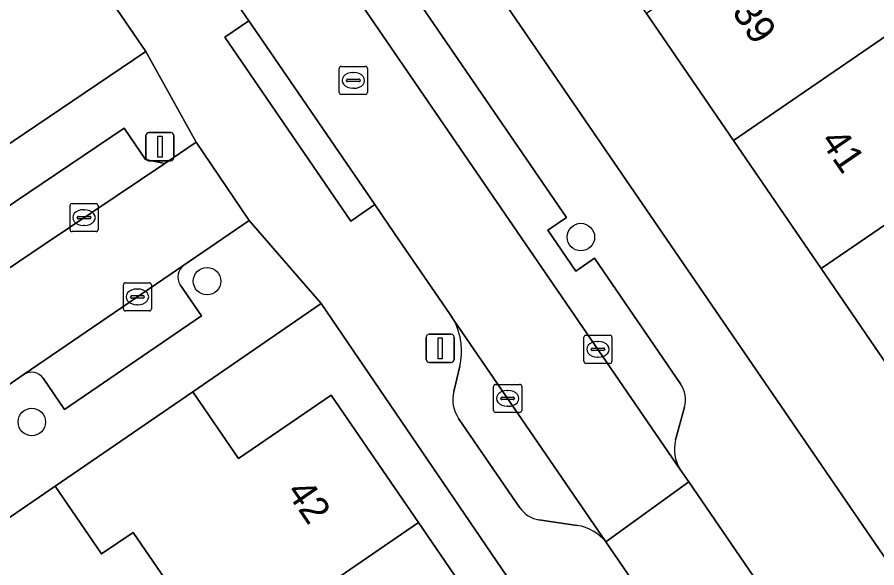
# Model space of a CAD drawing. Extents: x 157445 to 158888, y 383061 to 384688.
# Drawn here: x 158174.58 to 158205.18, y 383757.8 to 383777.4 of the extents above; entities that cross this region are included whole.
import ezdxf

# ---------------------------------------------------------------- set-up
doc = ezdxf.new("R2010")
doc.units = 0
for name, color, linetype in [('IMGEO_Boom', 7, 'Continuous'), ('IMGEO_Erf', 7, 'Continuous'), ('IMGEO_Kolk', 7, 'Continuous'), ('IMGEO_Lichtmast', 7, 'Continuous'), ('IMGEO_Pand', 7, 'Continuous'), ('IMGEO_Pand_nummerreeks', 7, 'Continuous'), ('IMGEO_Parkeervlak_open', 7, 'Continuous'), ('IMGEO_Rijbaan_lokaal_open', 7, 'Continuous'), ('IMGEO_Rioolput', 7, 'Continuous'), ('IMGEO_Voetpad_open', 7, 'Continuous')]:
    doc.layers.add(name, color=color, linetype=linetype)

msp = doc.modelspace()

# ---------------------------------------------------------------- linework, layer by layer
at = {"layer": 'IMGEO_Boom'}
for centre in [(158194.645, 383769.577), (158181.34, 383768.007), (158175.105, 383762.994)]:
    msp.add_circle(centre, 0.489, dxfattribs=at)
at = {"layer": 'IMGEO_Erf'}
for points in [[(158170.104, 383780.453), (158173.189, 383775.937), (158170.075, 383773.81), (158171.837, 383771.231), (158179.168, 383776.179), (158157.348, 383808.015)], [(158181.791, 383754.566), (158178.707, 383759.066), (158177.586, 383758.297), (158175.939, 383760.709), (158169.708, 383756.443)]]:
    msp.add_lwpolyline(points, dxfattribs=at)
for points in [[(158203.195, 383768.457), (158200.072, 383773.02), (158196.983, 383777.534), (158193.766, 383782.235), (158190.646, 383786.793), (158187.607, 383791.234), (158186.163, 383793.349), (158182.895, 383791.111), (158211.057, 383750), (158215.044, 383744.012), (158218.397, 383746.244), (158215.826, 383750), (158215.286, 383750.789), (158212.326, 383755.115), (158209.334, 383759.486), (158206.199, 383764.067)], [(158185.753, 383763.949), (158188.863, 383759.413), (158191.92, 383754.953), (158195.167, 383750.218), (158195.316, 383750), (158198.201, 383745.792), (158201.232, 383741.371), (158204.427, 383736.711), (158205.617, 383737.521), (158197.119, 383750), (158185.398, 383767.212), (158180.833, 383764.065), (158182.46, 383761.691)]]:
    msp.add_lwpolyline(points, close=True, dxfattribs=at)
at = {"layer": 'IMGEO_Kolk'}
for p, q in [((158176.464, 383769.844), (158176.464, 383770.696)), ((158176.539, 383770.77), (158177.391, 383770.77)), ((158177.465, 383770.696), (158177.465, 383769.844)), ((158176.952, 383770.55), (158176.977, 383770.55)), ((158176.723, 383770.264), (158176.723, 383770.276)), ((158177.161, 383770.227), (158176.763, 383770.227)), ((158176.766, 383770.313), (158177.164, 383770.313)), ((158177.207, 383770.276), (158177.207, 383770.264)), ((158176.975, 383769.99), (158176.95, 383769.99)), ((158177.391, 383769.77), (158176.539, 383769.77)), ((158178.437, 383767.948), (158179.289, 383767.948)), ((158178.362, 383767.022), (158178.362, 383767.874)), ((158178.85, 383767.728), (158178.875, 383767.728)), ((158179.363, 383767.874), (158179.363, 383767.022)), ((158178.621, 383767.442), (158178.621, 383767.454)), ((158179.059, 383767.405), (158178.661, 383767.405)), ((158178.664, 383767.491), (158179.062, 383767.491)), ((158179.105, 383767.454), (158179.105, 383767.442)), ((158178.873, 383767.168), (158178.848, 383767.168)), ((158179.289, 383766.948), (158178.437, 383766.948)), ((158194.751, 383765.156), (158194.751, 383766.008)), ((158194.826, 383766.082), (158195.678, 383766.082)), ((158195.239, 383765.862), (158195.264, 383765.862)), ((158195.752, 383766.008), (158195.752, 383765.156)), ((158195.01, 383765.576), (158195.01, 383765.588)), ((158195.448, 383765.539), (158195.05, 383765.539)), ((158195.053, 383765.625), (158195.451, 383765.625)), ((158195.494, 383765.588), (158195.494, 383765.576)), ((158195.262, 383765.302), (158195.237, 383765.302)), ((158195.678, 383765.082), (158194.826, 383765.082)), ((158191.612, 383764.333), (158192.464, 383764.333)), ((158191.537, 383763.407), (158191.537, 383764.259)), ((158192.025, 383764.113), (158192.05, 383764.113)), ((158192.538, 383764.259), (158192.538, 383763.407)), ((158191.796, 383763.827), (158191.796, 383763.839)), ((158192.234, 383763.79), (158191.836, 383763.79)), ((158191.839, 383763.876), (158192.237, 383763.876)), ((158192.28, 383763.839), (158192.28, 383763.827)), ((158192.048, 383763.553), (158192.023, 383763.553)), ((158192.464, 383763.333), (158191.612, 383763.333))]:
    msp.add_line(p, q, dxfattribs=at)
for points in [[(158176.464, 383769.844), (158176.464, 383770.696)], [(158176.539, 383770.77), (158177.391, 383770.77)], [(158177.465, 383770.696), (158177.465, 383769.844)], [(158177.391, 383769.77), (158176.539, 383769.77)], [(158178.437, 383767.948), (158179.289, 383767.948)], [(158178.362, 383767.022), (158178.362, 383767.874)], [(158179.363, 383767.874), (158179.363, 383767.022)], [(158179.289, 383766.948), (158178.437, 383766.948)], [(158194.751, 383765.156), (158194.751, 383766.008)], [(158194.826, 383766.082), (158195.678, 383766.082)], [(158195.752, 383766.008), (158195.752, 383765.156)], [(158195.678, 383765.082), (158194.826, 383765.082)], [(158191.612, 383764.333), (158192.464, 383764.333)], [(158191.537, 383763.407), (158191.537, 383764.259)], [(158192.538, 383764.259), (158192.538, 383763.407)], [(158192.464, 383763.333), (158191.612, 383763.333)]]:
    msp.add_lwpolyline(points, dxfattribs=at)
for centre, radius, start, end in [((158176.541, 383770.694), 0.0765, 91.552, 178.448), ((158176.541, 383770.694), 0.0765, 91.552, 178.448), ((158177.389, 383770.694), 0.0765, 1.552, 88.448), ((158177.389, 383770.694), 0.0765, 1.552, 88.448), ((158176.763, 383770.273), 0.0403, 85.8775, 175.7526), ((158176.76, 383770.263), 0.0366, 178.938, 274.7102), ((158177.164, 383770.27), 0.043, 264.8664, 352.4533), ((158177.168, 383770.275), 0.0386, 1.7309, 96.639), ((158176.541, 383769.846), 0.0765, 181.552, 268.448), ((158176.541, 383769.846), 0.0765, 181.552, 268.448), ((158177.389, 383769.846), 0.0765, 271.552, 358.448), ((158177.389, 383769.846), 0.0765, 271.552, 358.448), ((158178.439, 383767.872), 0.0765, 91.552, 178.448), ((158178.439, 383767.872), 0.0765, 91.552, 178.448), ((158179.287, 383767.872), 0.0765, 1.552, 88.448), ((158179.287, 383767.872), 0.0765, 1.552, 88.448), ((158178.661, 383767.451), 0.0403, 85.8775, 175.7526), ((158178.658, 383767.441), 0.0366, 178.938, 274.7102), ((158179.062, 383767.448), 0.043, 264.8664, 352.4533), ((158179.066, 383767.453), 0.0386, 1.7309, 96.639), ((158178.439, 383767.024), 0.0765, 181.552, 268.448), ((158178.439, 383767.024), 0.0765, 181.552, 268.448), ((158179.287, 383767.024), 0.0765, 271.552, 358.448), ((158179.287, 383767.024), 0.0765, 271.552, 358.448), ((158194.828, 383766.006), 0.0765, 91.552, 178.448), ((158194.828, 383766.006), 0.0765, 91.552, 178.448), ((158195.676, 383766.006), 0.0765, 1.552, 88.448), ((158195.676, 383766.006), 0.0765, 1.552, 88.448), ((158195.05, 383765.585), 0.0403, 85.8775, 175.7526), ((158195.047, 383765.575), 0.0366, 178.938, 274.7102), ((158195.451, 383765.582), 0.043, 264.8664, 352.4533), ((158195.455, 383765.587), 0.0386, 1.7309, 96.639), ((158194.828, 383765.158), 0.0765, 181.552, 268.448), ((158194.828, 383765.158), 0.0765, 181.552, 268.448), ((158195.676, 383765.158), 0.0765, 271.552, 358.448), ((158195.676, 383765.158), 0.0765, 271.552, 358.448), ((158191.614, 383764.257), 0.0765, 91.552, 178.448), ((158191.614, 383764.257), 0.0765, 91.552, 178.448), ((158192.462, 383764.257), 0.0765, 1.552, 88.448), ((158192.462, 383764.257), 0.0765, 1.552, 88.448), ((158191.836, 383763.836), 0.0403, 85.8775, 175.7526), ((158191.833, 383763.826), 0.0366, 178.938, 274.7102), ((158192.237, 383763.833), 0.043, 264.8664, 352.4533), ((158192.241, 383763.838), 0.0386, 1.7309, 96.639), ((158191.614, 383763.409), 0.0765, 181.552, 268.448), ((158191.614, 383763.409), 0.0765, 181.552, 268.448), ((158192.462, 383763.409), 0.0765, 271.552, 358.448), ((158192.462, 383763.409), 0.0765, 271.552, 358.448)]:
    msp.add_arc(centre, radius, start, end, dxfattribs=at)
for centre, major_axis, ratio, start_param, end_param in [((158176.951, 383770.27), (-0.387, 0.002), 0.722429, 4.712389, 7.853982), ((158176.976, 383770.27), (-0.39, 0.002), 0.717154, 1.570796, 4.712389), ((158178.849, 383767.448), (-0.387, 0.002), 0.722429, 4.712389, 7.853982), ((158178.874, 383767.448), (-0.39, 0.002), 0.717154, 1.570796, 4.712389), ((158195.238, 383765.582), (-0.387, 0.002), 0.722429, 4.712389, 7.853982), ((158195.263, 383765.582), (-0.39, 0.002), 0.717154, 1.570796, 4.712389), ((158192.024, 383763.833), (-0.387, 0.002), 0.722429, 4.712389, 7.853982), ((158192.049, 383763.833), (-0.39, 0.002), 0.717154, 1.570796, 4.712389)]:
    msp.add_ellipse(centre, major_axis=major_axis, ratio=ratio, start_param=start_param, end_param=end_param, dxfattribs=at)
at = {"layer": 'IMGEO_Lichtmast'}
for p, q in [((158179.168, 383772.395), (158179.168, 383773.195)), ((158179.168, 383773.195), (158179.168, 383772.395)), ((158179.268, 383773.295), (158180.058, 383773.295)), ((158180.058, 383773.295), (158179.268, 383773.295)), ((158180.158, 383773.195), (158180.158, 383772.395)), ((158180.158, 383772.395), (158180.158, 383773.195)), ((158180.058, 383772.295), (158179.268, 383772.295)), ((158179.268, 383772.295), (158180.058, 383772.295)), ((158189.243, 383766.117), (158190.033, 383766.117)), ((158190.033, 383766.117), (158189.243, 383766.117)), ((158189.143, 383765.217), (158189.143, 383766.017)), ((158189.143, 383766.017), (158189.143, 383765.217)), ((158190.133, 383766.017), (158190.133, 383765.217)), ((158190.133, 383765.217), (158190.133, 383766.017)), ((158190.033, 383765.117), (158189.243, 383765.117)), ((158189.243, 383765.117), (158190.033, 383765.117))]:
    msp.add_line(p, q, dxfattribs=at)
for points in [[(158179.588, 383773.17), (158179.738, 383773.17), (158179.738, 383772.42), (158179.588, 383772.42), (158179.588, 383773.17)], [(158189.563, 383765.992), (158189.713, 383765.992), (158189.713, 383765.242), (158189.563, 383765.242), (158189.563, 383765.992)]]:
    msp.add_lwpolyline(points, dxfattribs=at)
for centre, start, end in [((158179.268, 383773.195), 90, 180), ((158179.268, 383773.195), 90, 180), ((158180.058, 383773.195), 0, 90), ((158180.058, 383773.195), 360, 90), ((158179.268, 383772.395), 180, 270), ((158179.268, 383772.395), 180, 270), ((158180.058, 383772.395), 270, 0), ((158180.058, 383772.395), 270, 0), ((158189.243, 383766.017), 90, 180), ((158189.243, 383766.017), 90, 180), ((158190.033, 383766.017), 0, 90), ((158190.033, 383766.017), 360, 90), ((158189.243, 383765.217), 180, 270), ((158189.243, 383765.217), 180, 270), ((158190.033, 383765.217), 270, 0), ((158190.033, 383765.217), 270, 0)]:
    msp.add_arc(centre, 0.1, start, end, dxfattribs=at)
at = {"layer": 'IMGEO_Pand'}
for points in [[(158196.983, 383777.534), (158200.072, 383773.02), (158207.24, 383777.926), (158205.809, 383780.015), (158209.195, 383782.334), (158207.537, 383784.757), (158204.149, 383782.438)], [(158207.24, 383777.926), (158200.072, 383773.02), (158203.195, 383768.457), (158210.365, 383773.364)], [(158206.199, 383764.067), (158213.371, 383768.976), (158210.365, 383773.364), (158203.195, 383768.457)], [(158188.863, 383759.413), (158185.753, 383763.949), (158182.46, 383761.691), (158180.833, 383764.065), (158175.939, 383760.709), (158177.586, 383758.297), (158178.707, 383759.066), (158181.791, 383754.566)], [(158184.848, 383750.106), (158191.92, 383754.953), (158188.863, 383759.413), (158181.791, 383754.566)]]:
    msp.add_lwpolyline(points, close=True, dxfattribs=at)
at = {"layer": 'IMGEO_Parkeervlak_open'}
for points in [[(158180.633, 383786.925), (158198.181, 383761.303)], [(158198.194, 383764.347), (158195.13, 383768.82), (158194.463, 383768.363), (158193.465, 383769.82), (158194.133, 383770.277), (158186.834, 383780.933), (158186.166, 383780.475), (158185.336, 383781.687), (158186.005, 383782.145), (158183.563, 383785.71)], [(158174.159, 383768.371), (158175.539, 383769.31), (158179.837, 383772.198), (158179.151, 383772.335), (158178.389, 383773.452), (158173.531, 383770.179), (158174.291, 383769.066)], [(158180.511, 383768.576), (158174.828, 383764.691)], [(158175.508, 383764.55), (158176.268, 383763.437), (158181.14, 383766.768), (158180.38, 383767.881)], [(158195.535, 383758.724), (158190.126, 383766.615)], [(158190.334, 383764.979), (158190.119, 383764.083)], [(158198.017, 383762.354), (158198.334, 383763.519)], [(158190.295, 383763.124), (158192.476, 383759.938)], [(158193.154, 383759.513), (158194.513, 383759.311)]]:
    msp.add_lwpolyline(points, dxfattribs=at)
for centre, radius, start, end in [((158180.831, 383768.156), 0.528, 127.2771, 211.3741), ((158188.074, 383765.523), 2.324, 346.4646, 28.0267), ((158175.094, 383764.265), 0.502, 34.555, 122.0161), ((158197.367, 383763.781), 1.002, 344.82, 34.3739), ((158191.284, 383763.801), 1.198, 166.3903, 214.4086), ((158199.276, 383762.012), 1.304, 164.8054, 212.9327), ((158193.304, 383760.506), 1.005, 214.4507, 261.3867), ((158194.267, 383757.699), 1.631, 38.943, 81.314)]:
    msp.add_arc(centre, radius, start, end, dxfattribs=at)
at = {"layer": 'IMGEO_Rijbaan_lokaal_open'}
for points in [[(158179.656, 383781.899), (158179.858, 383781.604), (158182.01, 383778.474), (158182.833, 383777.276), (158183.462, 383776.361), (158187.315, 383770.733), (158188.017, 383769.707), (158189.996, 383766.816), (158190.126, 383766.615), (158195.535, 383758.724), (158198.486, 383760.859), (158198.181, 383761.303), (158180.633, 383786.925), (158176.948, 383792.302), (158167.359, 383806.297), (158164.805, 383810.025), (158161.728, 383807.983), (158162.085, 383807.463)], [(158174.159, 383768.371), (158172.941, 383767.542), (158164.897, 383762.069), (158163.604, 383761.185), (158165.587, 383758.374), (158167.014, 383759.349), (158173.626, 383763.869), (158174.828, 383764.691), (158180.511, 383768.576), (158182.841, 383770.169), (158180.957, 383772.951), (158179.837, 383772.198), (158175.539, 383769.31)], [(158200.771, 383757.522), (158198.486, 383760.859), (158195.535, 383758.724), (158197.821, 383755.384)]]:
    msp.add_lwpolyline(points, close=True, dxfattribs=at)
at = {"layer": 'IMGEO_Rioolput'}
for p, q in [((158186.121, 383775.653), (158186.973, 383775.653)), ((158186.046, 383774.727), (158186.046, 383775.579)), ((158186.534, 383775.433), (158186.559, 383775.433)), ((158187.047, 383775.579), (158187.047, 383774.727)), ((158186.305, 383775.147), (158186.305, 383775.159)), ((158186.743, 383775.11), (158186.345, 383775.11)), ((158186.348, 383775.196), (158186.746, 383775.196)), ((158186.789, 383775.159), (158186.789, 383775.147)), ((158186.557, 383774.873), (158186.532, 383774.873)), ((158186.973, 383774.653), (158186.121, 383774.653))]:
    msp.add_line(p, q, dxfattribs=at)
for points in [[(158186.121, 383775.653), (158186.973, 383775.653)], [(158186.046, 383774.727), (158186.046, 383775.579)], [(158187.047, 383775.579), (158187.047, 383774.727)], [(158186.973, 383774.653), (158186.121, 383774.653)]]:
    msp.add_lwpolyline(points, dxfattribs=at)
for centre, radius, start, end in [((158186.123, 383775.577), 0.0765, 91.552, 178.448), ((158186.123, 383775.577), 0.0765, 91.552, 178.448), ((158186.971, 383775.577), 0.0765, 1.552, 88.448), ((158186.971, 383775.577), 0.0765, 1.552, 88.448), ((158186.345, 383775.156), 0.0403, 85.8775, 175.7526), ((158186.342, 383775.146), 0.0366, 178.938, 274.7102), ((158186.746, 383775.153), 0.043, 264.8664, 352.4533), ((158186.75, 383775.158), 0.0386, 1.7309, 96.639), ((158186.123, 383774.729), 0.0765, 181.552, 268.448), ((158186.123, 383774.729), 0.0765, 181.552, 268.448), ((158186.971, 383774.729), 0.0765, 271.552, 358.448), ((158186.971, 383774.729), 0.0765, 271.552, 358.448)]:
    msp.add_arc(centre, radius, start, end, dxfattribs=at)
for centre, major_axis, ratio, start_param, end_param in [((158186.533, 383775.153), (-0.387, 0.002), 0.722429, 4.712389, 7.853982), ((158186.558, 383775.153), (-0.39, 0.002), 0.717154, 1.570796, 4.712389)]:
    msp.add_ellipse(centre, major_axis=major_axis, ratio=ratio, start_param=start_param, end_param=end_param, dxfattribs=at)
at = {"layer": 'IMGEO_Voetpad_open'}
for points in [[(158113.406, 383872.129), (158156.487, 383809.272), (158157.348, 383808.015), (158179.168, 383776.179), (158180.957, 383772.951), (158182.841, 383770.169), (158185.398, 383767.212), (158197.119, 383750), (158205.617, 383737.521)], [(158226.348, 383720.178), (158227.982, 383717.792), (158231.45, 383720.093), (158228.626, 383724.267), (158223.783, 383731.353), (158222.063, 383733.823), (158217.525, 383740.341), (158215.989, 383742.592), (158215.044, 383744.012), (158211.057, 383750), (158182.895, 383791.111), (158182.143, 383792.209), (158152.194, 383835.929)], [(158183.563, 383785.71), (158186.005, 383782.145), (158185.336, 383781.687), (158186.166, 383780.475), (158186.834, 383780.933), (158194.133, 383770.277), (158193.465, 383769.82), (158194.463, 383768.363), (158195.13, 383768.82), (158198.194, 383764.347)], [(158190.126, 383766.615), (158189.996, 383766.816), (158188.017, 383769.707), (158187.315, 383770.733), (158186.457, 383770.145), (158181.975, 383776.688), (158182.833, 383777.276), (158182.01, 383778.474), (158179.858, 383781.604), (158179.656, 383781.899)], [(158173.531, 383770.179), (158178.389, 383773.452), (158179.151, 383772.335), (158179.837, 383772.198), (158180.957, 383772.951), (158179.168, 383776.179), (158171.837, 383771.231), (158166.733, 383767.744), (158165.008, 383766.565), (158161.541, 383764.202), (158162.561, 383762.71), (158163.856, 383763.596), (158171.504, 383768.799), (158172.265, 383767.685)], [(158180.833, 383764.065), (158185.398, 383767.212), (158182.841, 383770.169), (158180.511, 383768.576)], [(158180.38, 383767.881), (158181.14, 383766.768), (158176.268, 383763.437), (158175.508, 383764.55)], [(158190.119, 383764.083), (158190.334, 383764.979)], [(158174.828, 383764.691), (158173.626, 383763.869)], [(158173.495, 383763.174), (158174.255, 383762.061), (158168.539, 383758.153), (158169.708, 383756.443), (158175.939, 383760.709), (158180.833, 383764.065)], [(158198.334, 383763.519), (158198.017, 383762.354)], [(158192.476, 383759.938), (158190.295, 383763.124)], [(158198.181, 383761.303), (158198.486, 383760.859), (158200.771, 383757.522), (158200.878, 383757.366)], [(158194.513, 383759.311), (158193.154, 383759.513)], [(158197.821, 383755.384), (158195.535, 383758.724)]]:
    msp.add_lwpolyline(points, dxfattribs=at)
msp.add_lwpolyline([(158182.833, 383777.276), (158181.975, 383776.688), (158186.457, 383770.145), (158187.315, 383770.733), (158183.462, 383776.361)], close=True, dxfattribs=at)
for centre, radius, start, end in [((158180.831, 383768.156), 0.528, 127.2771, 211.3741), ((158188.074, 383765.523), 2.324, 346.4646, 28.0267), ((158175.094, 383764.265), 0.502, 34.555, 122.0161), ((158197.367, 383763.781), 1.002, 344.82, 34.3739), ((158191.284, 383763.801), 1.198, 166.3903, 214.4086), ((158199.276, 383762.012), 1.304, 164.8054, 212.9327), ((158193.304, 383760.506), 1.005, 214.4507, 261.3867), ((158194.267, 383757.699), 1.631, 38.943, 81.314)]:
    msp.add_arc(centre, radius, start, end, dxfattribs=at)

# ---------------------------------------------------------------- texts
at = {"layer": 'IMGEO_Pand_nummerreeks'}
for s, rotation, p in [('39', 304.3867, (158199.997, 383777.592)), ('41', 304.3867, (158203.14, 383773)), ('42', 304.434, (158184.134, 383760.508))]:
    msp.add_text(s, height=1, rotation=rotation, dxfattribs=at).set_placement(p)

doc.saveas('drawing.dxf')
